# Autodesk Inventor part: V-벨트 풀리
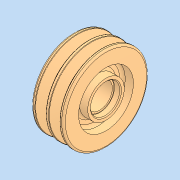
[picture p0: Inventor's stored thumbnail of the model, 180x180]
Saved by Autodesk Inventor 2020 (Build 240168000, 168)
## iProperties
Created: 2025-01
Part Number: V-벨트 풀리
Material: 강철, 주조
Document SubType Name: Modeling
Designer: 1강의실14
Density: 7.85 g/cm^3
Appearance: 기본값
Author: jhkim
Sending System: Autodesk Inventor 2025
Preprocessor: ST-DEVELOPER v20
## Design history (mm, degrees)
feature "솔리드1"
node "솔리드2"
